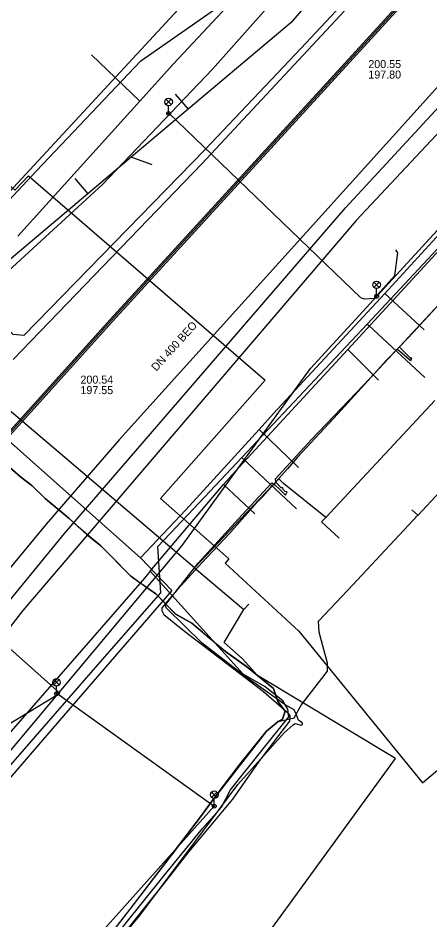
# Model space of a CAD drawing. Extents: x -598932 to -598196, y -1162210 to -1161504.
# Drawn here: x -598572.9 to -598531.7, y -1161789 to -1161698.8 of the extents above; entities that cross this region are included whole.
import ezdxf

# ---------------------------------------------------------------- set-up
doc = ezdxf.new("R2010")
doc.units = 0
for name, color, linetype in [('Vrstva 1', 7, 'Continuous'), ('Vrstva 12', 7, 'Continuous'), ('Vrstva 13', 7, 'Continuous'), ('Vrstva 14', 7, 'Continuous'), ('Vrstva 16', 7, 'Continuous'), ('Vrstva 33', 7, 'Continuous'), ('Vrstva 37', 7, 'Continuous'), ('Vrstva 4', 7, 'Continuous'), ('Vrstva 42', 7, 'Continuous'), ('Vrstva 54', 7, 'Continuous'), ('Vrstva 55', 7, 'Continuous'), ('Vrstva 58', 7, 'Continuous'), ('Vrstva 9', 7, 'Continuous')]:
    doc.layers.add(name, color=color, linetype=linetype)

msp = doc.modelspace()

# ---------------------------------------------------------------- linework, layer by layer
at = {"layer": 'Vrstva 1'}
for p, q in [((-598529.33, -1161703.86), (-598562.8, -1161740.95)), ((-598559.499, -1161713.451), (-598561.598, -1161712.701)), ((-598562.8, -1161740.95), (-598570.08, -1161749.41)), ((-598570.08, -1161749.41), (-598589.26, -1161772.42))]:
    msp.add_line(p, q, dxfattribs=at)
at = {"layer": 'Vrstva 12'}
for p, q in [((-598539.93, -1161731.92), (-598527.45, -1161718.36)), ((-598539.93, -1161731.92), (-598551.18, -1161744.13)), ((-598539.93, -1161731.92), (-598536.85, -1161735)), ((-598551.18, -1161744.13), (-598552.37, -1161745.43)), ((-598559.69, -1161754.11), (-598552.37, -1161745.43)), ((-598552.37, -1161745.43), (-598549.21, -1161748.37)), ((-598559.69, -1161754.11), (-598560.27, -1161754.79)), ((-598550.39, -1161764.41), (-598559.69, -1161754.11)), ((-598560.27, -1161754.79), (-598588.02, -1161786.62))]:
    msp.add_line(p, q, dxfattribs=at)
for points in [[(-598617.73, -1161753.57), (-598613.29, -1161752.78), (-598610.76, -1161755.12), (-598608.27, -1161755.41), (-598576.7, -1161719.3), (-598550.29, -1161690.77), (-598547.14, -1161687.36)], [(-598558.99, -1161814.68), (-598565.04, -1161809.62), (-598571.79, -1161804.23), (-598572.04, -1161803.79), (-598571.93, -1161803.22), (-598570.75, -1161800.57), (-598569.29, -1161798.59), (-598566.12, -1161794.52), (-598562.21, -1161789.43), (-598558.42, -1161784.7), (-598554.45, -1161779.83), (-598552.56, -1161777.68), (-598551.66, -1161775.97), (-598548.52, -1161772.02), (-598545.81, -1161768.66), (-598545.91, -1161767.89), (-598546.41, -1161767.06), (-598548.2, -1161765.65), (-598550.39, -1161764.41)]]:
    msp.add_lwpolyline(points, dxfattribs=at)
at = {"layer": 'Vrstva 13'}
for p, q in [((-598542.11, -1161748.73), (-598531.2, -1161737.02)), ((-598542.11, -1161748.73), (-598546.34, -1161745.32)), ((-598555.27, -1161753.75), (-598550.05, -1161748.25)), ((-598555.27, -1161753.75), (-598550.33, -1161757.94)), ((-598552.3, -1161761.22), (-598550.33, -1161757.94)), ((-598550.33, -1161757.94), (-598549.81, -1161757.38)), ((-598550.44, -1161762.87), (-598552.3, -1161761.22))]:
    msp.add_line(p, q, dxfattribs=at)
for points in [[(-598555.27, -1161753.75), (-598583.9, -1161729.43), (-598592.85, -1161739), (-598611.21, -1161756.79)], [(-598550.05, -1161748.25), (-598546.83, -1161744.85), (-598546.34, -1161745.32)], [(-598542.11, -1161748.73), (-598542.54, -1161749.17), (-598540.78, -1161750.8)], [(-598548.26, -1161790.83), (-598535.15, -1161772.84), (-598548.94, -1161764.53), (-598550.44, -1161762.87)]]:
    msp.add_lwpolyline(points, dxfattribs=at)
at = {"layer": 'Vrstva 14'}
for points in [[(-598597.949, -1161786.696), (-598594.355, -1161782.22), (-598591.124, -1161778.235), (-598590.488, -1161777.45), (-598568.259, -1161750.324), (-598540.145, -1161717.756), (-598494.895, -1161668.814), (-598474.946, -1161646.048), (-598446.726, -1161616.22), (-598420.512, -1161586.879), (-598391.532, -1161555.529), (-598341.416, -1161505.182)], [(-598573.404, -1161732.925), (-598571.604, -1161731.052), (-598554.514, -1161713.376), (-598533.774, -1161691.098), (-598513.523, -1161668.723), (-598504.735, -1161659.069), (-598494, -1161647.223), (-598480.574, -1161632.154), (-598477.858, -1161629.221), (-598469.826, -1161620.401), (-598456.055, -1161605.679), (-598446.117, -1161594.93), (-598428.638, -1161575.491)], [(-598449.055, -1161597.092), (-598451.08, -1161599.354), (-598469.948, -1161619.476), (-598481.318, -1161632.069), (-598500.359, -1161653.156), (-598508.903, -1161662.52), (-598516.704, -1161671.085), (-598523.517, -1161678.934), (-598531.97, -1161688.321), (-598542.658, -1161699.746), (-598544.581, -1161701.802), (-598554.215, -1161711.962), (-598572.329, -1161730.54), (-598573.411, -1161730.417), (-598574.926, -1161728.994), (-598576.936, -1161727.101), (-598579.192, -1161727.23), (-598579.92, -1161727.954)], [(-598589.947, -1161792.741), (-598577.445, -1161777.792), (-598565.596, -1161764.237), (-598559.546, -1161757.337), (-598558.635, -1161756.275), (-598558.918, -1161751.624), (-598555.314, -1161747.837), (-598550.53, -1161742.727), (-598537.985, -1161729.402), (-598525.355, -1161715.849), (-598512.719, -1161702.199), (-598500.184, -1161688.704), (-598495.944, -1161684.141), (-598496.644, -1161675.242), (-598493.647, -1161671.551), (-598491.273, -1161668.615), (-598474.912, -1161650.419), (-598466.442, -1161641.794), (-598445.99, -1161619.606), (-598438.518, -1161611.629), (-598437.483, -1161610.512)], [(-598537.985, -1161729.402), (-598537.832, -1161729.531), (-598532.206, -1161734.744)], [(-598550.53, -1161742.727), (-598550.38, -1161742.86), (-598545.063, -1161747.861)]]:
    msp.add_lwpolyline(points, dxfattribs=at)
at = {"layer": 'Vrstva 16'}
for p, q in [((-598536.23, -1161726.33), (-598532.29, -1161729.95)), ((-598548.8, -1161739.92), (-598544.87, -1161743.74))]:
    msp.add_line(p, q, dxfattribs=at)
for points in [[(-598584.21, -1161731.29), (-598584.25, -1161731.36), (-598584.27, -1161731.44), (-598584.28, -1161731.52), (-598584.28, -1161731.6), (-598584.26, -1161731.69), (-598584.25, -1161731.73), (-598584.21, -1161731.8), (-598584.14, -1161731.9), (-598584.11, -1161731.93), (-598579.83, -1161735.72), (-598571.74, -1161742.92), (-598560.67, -1161752.75), (-598556.13, -1161747.95), (-598548.8, -1161739.92), (-598547.35, -1161738.33), (-598536.23, -1161726.33), (-598530.7, -1161720.33), (-598528.8, -1161718.28), (-598523.82, -1161712.94), (-598516.92, -1161705.5), (-598511.95, -1161700.1), (-598506.77, -1161694.48)], [(-598581.16, -1161725.62), (-598581, -1161724.49), (-598579.19, -1161722.59), (-598576.04, -1161719.29), (-598575.28, -1161718.54), (-598571.05, -1161714.06), (-598560.62, -1161703.06), (-598550.73, -1161696.13)], [(-598560.67, -1161752.75), (-598557.52, -1161756.02), (-598568.8, -1161769.07), (-598584.98, -1161787.79), (-598587.03, -1161790.09), (-598589.52, -1161793.04), (-598597.01, -1161801.89), (-598611.83, -1161819.43), (-598616.42, -1161824.71), (-598624.01, -1161833.48), (-598624.6, -1161833.51)]]:
    msp.add_lwpolyline(points, dxfattribs=at)
at = {"layer": 'Vrstva 33'}
for p, q in [((-598558.109, -1161706.911), (-598557.579, -1161707.441)), ((-598558.109, -1161707.441), (-598557.579, -1161706.911)), ((-598557.844, -1161708.326), (-598557.844, -1161707.551)), ((-598537.305, -1161725.195), (-598536.775, -1161725.725)), ((-598537.305, -1161725.725), (-598536.775, -1161725.195)), ((-598537.04, -1161726.61), (-598537.04, -1161725.835)), ((-598569.323, -1161764.941), (-598568.793, -1161765.471)), ((-598569.323, -1161765.471), (-598568.793, -1161764.941)), ((-598569.058, -1161766.356), (-598569.058, -1161765.581)), ((-598553.543, -1161776.185), (-598553.013, -1161776.715)), ((-598553.543, -1161776.715), (-598553.013, -1161776.185)), ((-598553.278, -1161777.6), (-598553.278, -1161776.825))]:
    msp.add_line(p, q, dxfattribs=at)
for centre, radius in [((-598557.844, -1161707.176), 0.375), ((-598557.844, -1161708.326), 0.19), ((-598557.844, -1161708.326), 0.05), ((-598537.04, -1161725.46), 0.375), ((-598537.04, -1161726.61), 0.19), ((-598537.04, -1161726.61), 0.05), ((-598569.058, -1161765.206), 0.375), ((-598569.058, -1161766.356), 0.19), ((-598569.058, -1161766.356), 0.05), ((-598553.278, -1161776.45), 0.375), ((-598553.278, -1161777.6), 0.19), ((-598553.278, -1161777.6), 0.05)]:
    msp.add_circle(centre, radius, dxfattribs=at)
at = {"layer": 'Vrstva 37'}
for points in [[(-598574.47, -1161712.239), (-598573.671, -1161712.994), (-598575.046, -1161714.446), (-598573.23, -1161716.013), (-598571.855, -1161714.561), (-598548.196, -1161734.981), (-598558.65, -1161746.819), (-598552.72, -1161752.07)], [(-598552.72, -1161752.07), (-598551.81, -1161752.876), (-598552.196, -1161753.296), (-598544.822, -1161760.111)], [(-598544.822, -1161760.111), (-598532.436, -1161775.263), (-598529.423, -1161772.685), (-598511.017, -1161794.939), (-598514.081, -1161797.83), (-598490.733, -1161827.358), (-598495.709, -1161833.586), (-598474.045, -1161850.906)]]:
    msp.add_lwpolyline(points, dxfattribs=at)
at = {"layer": 'Vrstva 42'}
for points in [[(-598482.625, -1161640.144), (-598482.467, -1161640.638), (-598493.794, -1161653.11), (-598495.271, -1161654.682), (-598509.79, -1161670.452), (-598509.789, -1161670.451), (-598514.544, -1161675.66), (-598514.586, -1161675.706), (-598563.469, -1161729.131), (-598604.648, -1161774.799), (-598616.464, -1161788.466), (-598628.603, -1161803.794)], [(-598628.837, -1161803.606), (-598616.696, -1161788.274), (-598604.872, -1161774.601), (-598563.691, -1161728.929), (-598514.958, -1161675.668), (-598514.766, -1161675.458), (-598510.011, -1161670.249), (-598510.01, -1161670.248), (-598495.509, -1161654.498), (-598494.886, -1161653.538)], [(-598628.837, -1161803.606), (-598616.696, -1161788.274), (-598604.872, -1161774.601), (-598563.691, -1161728.929), (-598514.958, -1161675.668), (-598514.766, -1161675.458), (-598510.011, -1161670.249), (-598510.01, -1161670.248), (-598495.509, -1161654.498), (-598494.886, -1161653.538)], [(-598722.434, -1161887.506), (-598721.303, -1161887.465), (-598711.981, -1161877.933), (-598701.016, -1161865.728), (-598698.292, -1161862.397), (-598697.293, -1161861.83), (-598689.452, -1161859.77), (-598688.12, -1161859.789), (-598687.331, -1161860.531), (-598681.484, -1161865.606), (-598680.195, -1161866.255), (-598678.811, -1161865.236), (-598675.692, -1161860.773), (-598673.236, -1161858.028), (-598665.054, -1161848.125), (-598640.034, -1161817.645), (-598628.603, -1161803.794), (-598616.464, -1161788.466), (-598604.648, -1161774.799), (-598563.469, -1161729.131), (-598514.586, -1161675.706), (-598514.881, -1161675.495)], [(-598514.841, -1161675.57), (-598514.772, -1161675.687), (-598563.58, -1161729.03), (-598604.76, -1161774.7), (-598616.58, -1161788.37), (-598628.72, -1161803.7), (-598640.15, -1161817.55), (-598650.17, -1161829.78), (-598665.17, -1161848.03), (-598673.35, -1161857.93), (-598675.81, -1161860.68), (-598678.92, -1161865.13), (-598680.21, -1161866.08), (-598681.4, -1161865.48), (-598687.23, -1161860.42), (-598688.06, -1161859.64), (-598689.47, -1161859.62), (-598697.35, -1161861.69), (-598698.39, -1161862.28), (-598701.13, -1161865.63), (-598712.09, -1161877.83), (-598721.41, -1161887.36)], [(-598538.602, -1161726.764), (-598538.297, -1161726.873), (-598537.236, -1161726.792), (-598535.21, -1161724.516), (-598534.929, -1161722.254), (-598535.118, -1161721.955)], [(-598564.53, -1161793.1), (-598560.86, -1161788.71), (-598558.336, -1161785.312), (-598557.57, -1161784.28), (-598553.81, -1161779.34), (-598550.93, -1161775.43), (-598548.611, -1161772.856), (-598546.28, -1161770.27), (-598545.39, -1161769.45), (-598545.18, -1161769.34), (-598544.584, -1161769.481), (-598544.44, -1161769.44), (-598544.444, -1161769.296), (-598544.86, -1161768.98), (-598545.06, -1161768.47), (-598545.29, -1161767.96), (-598546.2, -1161767.46), (-598550.35, -1161764.5), (-598554.48, -1161761.31), (-598558.04, -1161757.84), (-598558.15, -1161757.6), (-598558.11, -1161757.43), (-598556.944, -1161755.938), (-598554.89, -1161753.31), (-598550.87, -1161748.85), (-598547.518, -1161745.262), (-598547.331, -1161745.394), (-598547.177, -1161745.503), (-598546.761, -1161745.882), (-598546.599, -1161746.053), (-598546.149, -1161746.5), (-598545.984, -1161746.163), (-598546.197, -1161746.128), (-598546.394, -1161745.943), (-598546.411, -1161745.767), (-598546.591, -1161745.752), (-598547.119, -1161745.206), (-598547.125, -1161745.162), (-598547.17, -1161744.864), (-598543.55, -1161740.94), (-598538.35, -1161735.48), (-598537.249, -1161734.314), (-598534.976, -1161731.907), (-598534.76, -1161732.067), (-598533.76, -1161732.939), (-598533.615, -1161733.043), (-598533.501, -1161732.811), (-598533.634, -1161732.783), (-598534.713, -1161731.727), (-598534.681, -1161731.585), (-598534.68, -1161731.58), (-598533.1, -1161729.86), (-598529.409, -1161725.927)], [(-598529.409, -1161725.927), (-598532.32, -1161729.06), (-598533.34, -1161730.21), (-598534.681, -1161731.585), (-598536.09, -1161733.03), (-598537.249, -1161734.314), (-598540.91, -1161738.37), (-598544.96, -1161742.69), (-598545.96, -1161743.85), (-598547.125, -1161745.162), (-598547.331, -1161745.394), (-598548.42, -1161746.62), (-598548.95, -1161747.17), (-598551.77, -1161750.32), (-598554.54, -1161753.27), (-598556.944, -1161755.938), (-598557.18, -1161756.2), (-598558.53, -1161757.76), (-598558.52, -1161758.03), (-598558.32, -1161758.42), (-598556.25, -1161760.11), (-598548.36, -1161766.12), (-598545.98, -1161768.19), (-598545.72, -1161768.55), (-598545.74, -1161769.09), (-598546.86, -1161770.54), (-598548.611, -1161772.856), (-598548.81, -1161773.12), (-598551.45, -1161776.91), (-598555.96, -1161782.31), (-598558.336, -1161785.312), (-598560.1, -1161787.54), (-598563.57, -1161791.88)], [(-598565.85, -1161793.25), (-598561.69, -1161787.9), (-598557.5, -1161782.39), (-598554.45, -1161778.38), (-598553.39, -1161776.93), (-598552.36, -1161775.56), (-598550.69, -1161773.35), (-598548.04, -1161770.09), (-598546.9, -1161769.13), (-598546.45, -1161768.91), (-598546.2, -1161768.08), (-598546.92, -1161767.12), (-598547.36, -1161765.83), (-598550.07, -1161763.62), (-598552.16, -1161762.14), (-598553.25, -1161761.24), (-598553.96, -1161760.66), (-598554.47, -1161760.2), (-598555.52, -1161759.31), (-598557.14, -1161758.4), (-598559.11, -1161756.36), (-598560.82, -1161755.18), (-598561.64, -1161754.59), (-598563.69, -1161752.5), (-598564.63, -1161751.56), (-598565.92, -1161750.51), (-598566.88, -1161749.65), (-598567.82, -1161748.79), (-598570.18, -1161746.83), (-598571.52, -1161745.54), (-598572.66, -1161744.66), (-598574.86, -1161742.76)]]:
    msp.add_lwpolyline(points, dxfattribs=at)
at = {"layer": 'Vrstva 54'}
for p, q in [((-598538.619, -1161726.758), (-598557.871, -1161708.254)), ((-598568.721, -1161766.31), (-598595.679, -1161742.213))]:
    msp.add_line(p, q, dxfattribs=at)
msp.add_lwpolyline([(-598663.206, -1161879.566), (-598645.593, -1161831.834), (-598628.289, -1161810.908), (-598613.766, -1161793.569), (-598568.721, -1161766.31)], dxfattribs=at)
at = {"layer": 'Vrstva 55'}
for points in [[(-598593.724, -1161815.599), (-598601.79, -1161825.2), (-598612.66, -1161816.58), (-598605.21, -1161808.89), (-598597.75, -1161800.73), (-598596.12, -1161801.43), (-598593.55, -1161803.29), (-598583.76, -1161792.8), (-598587.73, -1161788.84), (-598556.49, -1161751.54), (-598543.66, -1161733.82), (-598504.5, -1161691.15), (-598500.07, -1161684.86), (-598483.28, -1161665.74), (-598469.525, -1161651.138), (-598469.135, -1161651.28), (-598469.525, -1161651.138), (-598431.76, -1161609.32), (-598365.821, -1161539.037), (-598342.93, -1161515.615), (-598331.661, -1161505.182)], [(-598635.02, -1161725.8), (-598623.513, -1161743.463), (-598608.12, -1161722.98), (-598608.22, -1161717.163), (-598608.12, -1161722.98), (-598623.249, -1161743.568), (-598610.78, -1161754.69), (-598601.71, -1161758.3), (-598595.65, -1161746.64), (-598593.576, -1161744.441), (-598595.719, -1161742.325), (-598593.576, -1161744.441), (-598591.036, -1161741.822), (-598575.14, -1161725.19), (-598564.458, -1161715.417), (-598553.451, -1161703.881), (-598547.789, -1161697.531), (-598546.625, -1161695.044), (-598548.56, -1161692.55), (-598559.49, -1161681.15), (-598556.019, -1161677.263), (-598556.805, -1161676.476)], [(-598568.909, -1161766.4), (-598553.278, -1161777.6), (-598569.547, -1161795.783), (-598573.367, -1161800.405), (-598583.753, -1161792.927), (-598593.492, -1161803.266), (-598595.8, -1161801.466), (-598597.739, -1161800.866), (-598612.833, -1161816.606), (-598601.847, -1161825.192), (-598593.723, -1161815.545)]]:
    msp.add_lwpolyline(points, dxfattribs=at)
at = {"layer": 'Vrstva 58'}
for p, q in [((-598560.74, -1161707.09), (-598565.57, -1161702.48)), ((-598572.93, -1161720.6), (-598560.74, -1161707.09)), ((-598532.92, -1161748.5), (-598533.52, -1161747.95))]:
    msp.add_line(p, q, dxfattribs=at)
for points in [[(-598560.74, -1161707.09), (-598557.35, -1161703.37), (-598551.98, -1161697.64), (-598550.26, -1161696.98), (-598549.09, -1161695.78)], [(-598532.932, -1161748.513), (-598530.69, -1161746.13), (-598520.45, -1161734.95), (-598519.84, -1161734.25), (-598513.2, -1161727.09), (-598507.18, -1161720.81), (-598507.2, -1161718.91), (-598502.89, -1161714.09)], [(-598574.86, -1161742.76), (-598572.66, -1161744.66), (-598571.52, -1161745.54), (-598570.18, -1161746.83), (-598567.82, -1161748.79), (-598565.95, -1161750.51), (-598564.63, -1161751.56), (-598561.64, -1161754.59), (-598559.11, -1161756.36), (-598557.15, -1161758.39), (-598555.52, -1161759.31), (-598552.16, -1161762.14), (-598550.01, -1161763.67), (-598547.36, -1161765.83), (-598546.92, -1161767.12), (-598546.2, -1161768.08), (-598546.45, -1161768.91), (-598546.9, -1161769.13)], [(-598565.85, -1161793.25), (-598561.69, -1161787.9), (-598557.5, -1161782.39), (-598554.45, -1161778.38), (-598553.39, -1161776.93), (-598552.36, -1161775.56), (-598550.69, -1161773.35), (-598548.04, -1161770.09), (-598546.9, -1161769.13), (-598546.45, -1161768.91), (-598546.2, -1161768.08), (-598546.92, -1161767.12), (-598547.36, -1161765.83), (-598550.07, -1161763.62), (-598552.16, -1161762.14), (-598553.25, -1161761.24), (-598553.96, -1161760.66), (-598554.47, -1161760.2), (-598555.52, -1161759.31), (-598557.14, -1161758.4), (-598559.11, -1161756.36), (-598560.82, -1161755.18), (-598561.64, -1161754.59), (-598563.69, -1161752.5), (-598564.63, -1161751.56), (-598565.92, -1161750.51), (-598566.88, -1161749.65), (-598567.82, -1161748.79), (-598570.18, -1161746.83), (-598571.52, -1161745.54), (-598572.66, -1161744.66), (-598574.86, -1161742.76)], [(-598546.9, -1161769.13), (-598545.3, -1161768.76), (-598544.59, -1161767.5), (-598541.96, -1161764.08), (-598541.94, -1161763.28), (-598542.79, -1161760.2), (-598542.84, -1161759.1), (-598539.93, -1161755.99), (-598539.45, -1161755.48), (-598532.92, -1161748.5)], [(-598546.9, -1161769.13), (-598548.04, -1161770.09), (-598553.39, -1161776.93), (-598554.45, -1161778.38), (-598557.5, -1161782.39), (-598565.85, -1161793.25), (-598568.28, -1161796.41), (-598571.24, -1161799.93), (-598571.94, -1161802.27), (-598572.89, -1161803.43)]]:
    msp.add_lwpolyline(points, dxfattribs=at)
at = {"layer": 'Vrstva 9'}
for p, q in [((-598506.43, -1161684.15), (-598539.1, -1161719.04)), ((-598557.202, -1161706.383), (-598555.907, -1161707.907)), ((-598567.216, -1161714.823), (-598565.921, -1161716.347)), ((-598539.1, -1161719.04), (-598572.43, -1161758.03)), ((-598572.43, -1161758.03), (-598587.489, -1161777.24))]:
    msp.add_line(p, q, dxfattribs=at)
for points in [[(-598515.2, -1161664.4), (-598526.935, -1161677.85), (-598529.823, -1161681.159), (-598534.89, -1161686.968), (-598544.811, -1161698.34), (-598545.587, -1161699.229)], [(-598545.587, -1161699.229), (-598555.907, -1161707.907), (-598561.598, -1161712.701), (-598565.921, -1161716.347), (-598585.65, -1161732.96)]]:
    msp.add_lwpolyline(points, dxfattribs=at)

# ---------------------------------------------------------------- texts
at = {"layer": 'Vrstva 4'}
for s, p in [('200.55', (-598537.867, -1161703.787)), ('197.80', (-598537.867, -1161704.837)), ('200.54', (-598566.665, -1161735.342)), ('197.55', (-598566.665, -1161736.392))]:
    msp.add_text(s, height=0.8, dxfattribs=at).set_placement(p)
msp.add_text('DN 400 BEO', height=0.8, rotation=48, dxfattribs=at).set_placement((-598559.07, -1161734.155))

doc.saveas('drawing.dxf')
